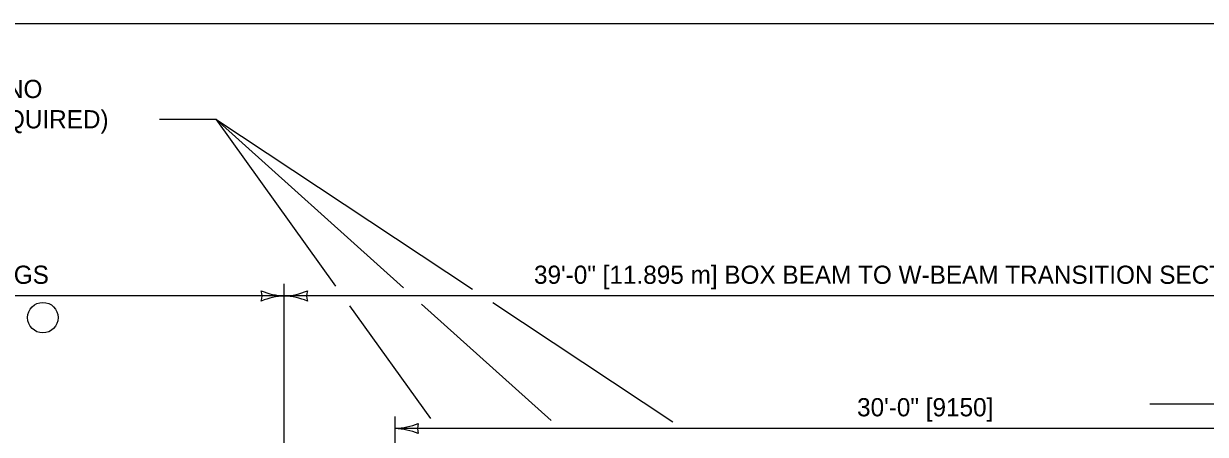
# Model space of a CAD drawing. Extents: x 49991.4 to 50021, y 49987.6 to 50011.4.
# Drawn here: x 50001.42 to 50005.32, y 49997.645 to 49998.999 of the extents above; entities that cross this region are included whole.
import ezdxf

# ---------------------------------------------------------------- set-up
doc = ezdxf.new("R2010")
doc.units = 0
for name, color, linetype in [('Level 1', 7, 'Continuous'), ('Level 2', 7, 'Continuous'), ('Level 3', 7, 'Continuous')]:
    doc.layers.add(name, color=color, linetype=linetype)

msp = doc.modelspace()

# ---------------------------------------------------------------- linework, layer by layer
at = {"layer": 'Level 1'}
msp.add_lwpolyline([(49999.3835, 49998.9992), (50016.7501, 49998.9992), (50016.7501, 49987.7988), (49999.3835, 49987.7988)], close=True, dxfattribs=at)
at = {"layer": 'Level 2'}
msp.add_circle((50001.4835, 49998.0297), 0.0503, dxfattribs=at)
at = {"layer": 'Level 3'}
for p, q in [((50001.8685, 49998.6839), (50002.0538, 49998.6839)), ((50002.0538, 49998.6839), (50002.449, 49998.1337)), ((50002.0538, 49998.6839), (50002.6738, 49998.1279)), ((50002.0538, 49998.6839), (50002.9015, 49998.1233)), ((50002.2804, 49997.2851), (50002.2804, 49998.1412)), ((50002.2804, 49998.1012), (50000.1279, 49998.1012)), ((50007.0384, 49998.1012), (50002.2804, 49998.1012)), ((50002.4957, 49998.0687), (50002.7629, 49997.6967)), ((50002.7334, 49998.0745), (50003.1611, 49997.6909)), ((50002.9683, 49998.0791), (50003.5623, 49997.6863)), ((50007.5344, 49997.7442), (50005.1367, 49997.7442)), ((50002.6464, 49996.8492), (50002.6464, 49997.7042)), ((50006.2837, 49997.6642), (50002.6464, 49997.6642))]:
    msp.add_line(p, q, dxfattribs=at)
for centre, radius, start, end in [((50002.1522, 49998.1012), 0.0548, 342.1388, 17.8612), ((50002.2919, 49998.3339), 0.233, 247.9228, 267.1727), ((50002.2712, 49998.3233), 0.2223, 272.3605, 292.544), ((50002.4086, 49998.1012), 0.0548, 162.1388, 197.8612), ((50002.2896, 49997.8791), 0.2223, 92.3605, 112.544), ((50002.2689, 49997.8685), 0.233, 67.9228, 87.1727), ((50002.6372, 49997.8864), 0.2223, 272.3605, 292.544), ((50002.7746, 49997.6642), 0.0548, 162.1388, 197.8612), ((50002.6349, 49997.4315), 0.233, 67.9228, 87.1727)]:
    msp.add_arc(centre, radius, start, end, dxfattribs=at)

# ---------------------------------------------------------------- texts
at = {"layer": 'Level 2'}
for s, p in [('3 INTERMEDIATE POSTS (NO', (50000.3541, 49998.7539)), ('CONNECTION TO RAIL REQUIRED)', (50000.3541, 49998.6539))]:
    msp.add_text(s, height=0.06, rotation=360, dxfattribs=at).set_placement(p)
for s, p in [('STANDARD MGS', (50000.857, 49998.1412)), ('39\'-0" [11.895 m] BOX BEAM TO W-BEAM TRANSITION SECTION PAY LIMITS', (50003.1044, 49998.1412)), ('30\'-0" [9150]', (50004.1706, 49997.7042))]:
    msp.add_text(s, height=0.06, dxfattribs=at).set_placement(p)

doc.saveas('drawing.dxf')
